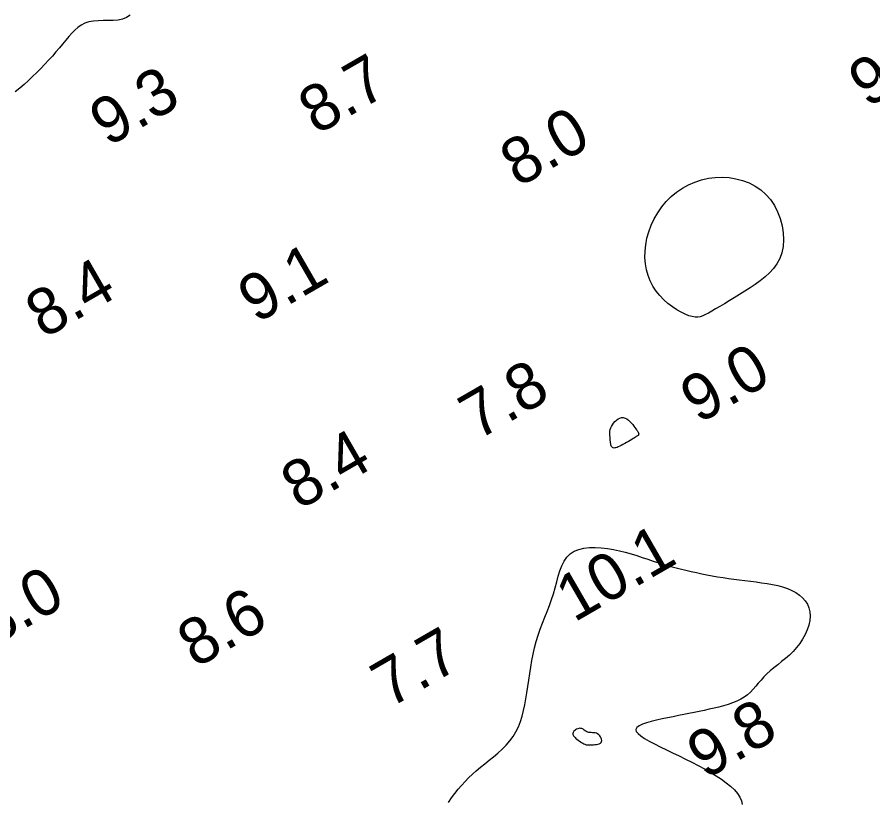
# Model space of a CAD drawing. Extents: x 3024098 to 3056816, y 418252 to 509144.
# Drawn here: x 3036706.3 to 3036798.1, y 419406.4 to 419490.6 of the extents above; entities that cross this region are included whole.
import ezdxf

# ---------------------------------------------------------------- set-up
doc = ezdxf.new("R2010")
doc.units = 0
doc.layers.add('V-CHAN-CONT-EL10', color=7, linetype='Continuous')
doc.layers.add('V-TOPO-SOUN-0911', color=7, linetype='Continuous')

msp = doc.modelspace()

# ---------------------------------------------------------------- linework, layer by layer
at = {"layer": 'V-CHAN-CONT-EL10'}
for points in [[(3036718.397, 419490.77), (3036718.028, 419490.524), (3036717.597, 419490.359), (3036717.117, 419490.264), (3036716.601, 419490.218), (3036716.064, 419490.203), (3036715.519, 419490.2), (3036714.982, 419490.19), (3036714.466, 419490.153), (3036713.985, 419490.07), (3036713.55, 419489.928), (3036713.157, 419489.728), (3036712.795, 419489.476), (3036712.457, 419489.18), (3036712.133, 419488.846), (3036711.815, 419488.48), (3036711.495, 419488.09), (3036711.162, 419487.681), (3036710.812, 419487.26), (3036710.442, 419486.83), (3036710.056, 419486.393), (3036709.654, 419485.952), (3036709.239, 419485.508), (3036708.813, 419485.065), (3036708.377, 419484.625), (3036707.933, 419484.191), (3036707.482, 419483.764), (3036707.022, 419483.349), (3036706.55, 419482.949), (3036706.062, 419482.567)], [(3036752.581, 419406.217), (3036752.921, 419406.715), (3036753.266, 419407.187), (3036753.62, 419407.634), (3036753.983, 419408.059), (3036754.358, 419408.467), (3036754.746, 419408.861), (3036755.149, 419409.245), (3036755.57, 419409.622), (3036756.01, 419409.996), (3036756.47, 419410.371), (3036756.942, 419410.749), (3036757.416, 419411.135), (3036757.885, 419411.533), (3036758.339, 419411.945), (3036758.768, 419412.375), (3036759.165, 419412.828), (3036759.519, 419413.305), (3036759.825, 419413.811), (3036760.085, 419414.343), (3036760.305, 419414.902), (3036760.491, 419415.483), (3036760.648, 419416.087), (3036760.782, 419416.71), (3036760.899, 419417.352), (3036761.005, 419418.011), (3036761.104, 419418.684), (3036761.202, 419419.368), (3036761.302, 419420.06), (3036761.409, 419420.756), (3036761.528, 419421.453), (3036761.663, 419422.147), (3036761.817, 419422.835), (3036761.996, 419423.513), (3036762.201, 419424.178), (3036762.428, 419424.832), (3036762.67, 419425.478), (3036762.919, 419426.116), (3036763.169, 419426.75), (3036763.412, 419427.381), (3036763.641, 419428.013), (3036763.85, 419428.646), (3036764.035, 419429.282), (3036764.204, 419429.911), (3036764.373, 419430.522), (3036764.552, 419431.104), (3036764.757, 419431.646), (3036764.999, 419432.138), (3036765.292, 419432.568), (3036765.649, 419432.925), (3036766.078, 419433.201), (3036766.573, 419433.4), (3036767.123, 419433.53), (3036767.716, 419433.597), (3036768.34, 419433.609), (3036768.985, 419433.574), (3036769.639, 419433.498), (3036770.291, 419433.388), (3036770.931, 419433.252), (3036771.56, 419433.094), (3036772.178, 419432.919), (3036772.787, 419432.732), (3036773.387, 419432.538), (3036773.981, 419432.341), (3036774.57, 419432.146), (3036775.155, 419431.957), (3036775.737, 419431.779), (3036776.317, 419431.612), (3036776.895, 419431.454), (3036777.471, 419431.306), (3036778.045, 419431.166), (3036778.619, 419431.035), (3036779.191, 419430.91), (3036779.763, 419430.793), (3036780.335, 419430.681), (3036780.907, 419430.575), (3036781.48, 419430.474), (3036782.056, 419430.379), (3036782.635, 419430.289), (3036783.218, 419430.203), (3036783.806, 419430.123), (3036784.4, 419430.047), (3036784.999, 419429.975), (3036785.6, 419429.902), (3036786.198, 419429.825), (3036786.788, 419429.739), (3036787.364, 419429.638), (3036787.922, 419429.519), (3036788.456, 419429.376), (3036788.961, 419429.206), (3036789.433, 419429.004), (3036789.866, 419428.769), (3036790.256, 419428.502), (3036790.597, 419428.204), (3036790.885, 419427.873), (3036791.113, 419427.511), (3036791.279, 419427.117), (3036791.376, 419426.692), (3036791.4, 419426.237), (3036791.357, 419425.758), (3036791.25, 419425.265), (3036791.086, 419424.764), (3036790.869, 419424.265), (3036790.604, 419423.776), (3036790.298, 419423.304), (3036789.954, 419422.857), (3036789.579, 419422.443), (3036789.181, 419422.056), (3036788.767, 419421.694), (3036788.347, 419421.349), (3036787.929, 419421.016), (3036787.521, 419420.691), (3036787.131, 419420.367), (3036786.768, 419420.041), (3036786.438, 419419.707), (3036786.134, 419419.369), (3036785.846, 419419.032), (3036785.565, 419418.701), (3036785.283, 419418.381), (3036784.989, 419418.076), (3036784.675, 419417.791), (3036784.331, 419417.531), (3036783.95, 419417.299), (3036783.534, 419417.094), (3036783.088, 419416.912), (3036782.616, 419416.749), (3036782.124, 419416.603), (3036781.614, 419416.469), (3036781.092, 419416.345), (3036780.563, 419416.228), (3036780.03, 419416.113), (3036779.492, 419416), (3036778.949, 419415.888), (3036778.399, 419415.776), (3036777.841, 419415.664), (3036777.273, 419415.55), (3036776.695, 419415.434), (3036776.105, 419415.315), (3036775.505, 419415.192), (3036774.913, 419415.063), (3036774.35, 419414.927), (3036773.837, 419414.781), (3036773.395, 419414.624), (3036773.045, 419414.455), (3036772.807, 419414.27), (3036772.703, 419414.069), (3036772.747, 419413.85), (3036772.93, 419413.613), (3036773.233, 419413.361), (3036773.64, 419413.093), (3036774.135, 419412.811), (3036774.699, 419412.516), (3036775.317, 419412.209), (3036775.971, 419411.892), (3036776.646, 419411.565), (3036777.334, 419411.229), (3036778.026, 419410.886), (3036778.716, 419410.536), (3036779.397, 419410.179), (3036780.061, 419409.818), (3036780.701, 419409.453), (3036781.311, 419409.085), (3036781.882, 419408.714), (3036782.406, 419408.34), (3036782.875, 419407.963), (3036783.281, 419407.582), (3036783.615, 419407.197), (3036783.868, 419406.807), (3036784.033, 419406.411), (3036784.101, 419406.009)]]:
    msp.add_lwpolyline(points, dxfattribs=at)
for points in [[(3036774.524, 419461.673), (3036774.238, 419462.232), (3036774.009, 419462.822), (3036773.838, 419463.44), (3036773.725, 419464.082), (3036773.673, 419464.745), (3036773.683, 419465.424), (3036773.755, 419466.117), (3036773.893, 419466.82), (3036774.092, 419467.523), (3036774.353, 419468.22), (3036774.672, 419468.902), (3036775.048, 419469.56), (3036775.478, 419470.186), (3036775.96, 419470.771), (3036776.493, 419471.307), (3036777.074, 419471.787), (3036777.697, 419472.207), (3036778.356, 419472.566), (3036779.044, 419472.863), (3036779.756, 419473.095), (3036780.486, 419473.26), (3036781.226, 419473.357), (3036781.971, 419473.384), (3036782.714, 419473.34), (3036783.446, 419473.223), (3036784.16, 419473.034), (3036784.847, 419472.771), (3036785.498, 419472.435), (3036786.104, 419472.025), (3036786.657, 419471.54), (3036787.149, 419470.981), (3036787.571, 419470.348), (3036787.92, 419469.658), (3036788.194, 419468.927), (3036788.391, 419468.172), (3036788.509, 419467.411), (3036788.544, 419466.662), (3036788.496, 419465.94), (3036788.36, 419465.265), (3036788.138, 419464.648), (3036787.838, 419464.088), (3036787.469, 419463.576), (3036787.041, 419463.105), (3036786.566, 419462.67), (3036786.053, 419462.261), (3036785.512, 419461.873), (3036784.953, 419461.498), (3036784.387, 419461.13), (3036783.821, 419460.771), (3036783.263, 419460.425), (3036782.72, 419460.095), (3036782.2, 419459.783), (3036781.711, 419459.493), (3036781.259, 419459.229), (3036780.853, 419458.993), (3036780.496, 419458.789), (3036780.18, 419458.62), (3036779.89, 419458.488), (3036779.614, 419458.398), (3036779.339, 419458.351), (3036779.051, 419458.351), (3036778.739, 419458.401), (3036778.388, 419458.504), (3036777.99, 419458.663), (3036777.553, 419458.874), (3036777.092, 419459.138), (3036776.618, 419459.45), (3036776.145, 419459.81), (3036775.687, 419460.214), (3036775.255, 419460.661), (3036774.864, 419461.148)], [(3036770.144, 419444.392), (3036770.095, 419444.461), (3036770.055, 419444.543), (3036770.023, 419444.631), (3036769.998, 419444.724), (3036769.98, 419444.816), (3036769.967, 419444.904), (3036769.958, 419444.983), (3036769.952, 419445.05), (3036769.948, 419445.108), (3036769.945, 419445.161), (3036769.944, 419445.212), (3036769.942, 419445.265), (3036769.938, 419445.325), (3036769.933, 419445.394), (3036769.925, 419445.476), (3036769.914, 419445.575), (3036769.904, 419445.69), (3036769.897, 419445.819), (3036769.9, 419445.96), (3036769.914, 419446.113), (3036769.945, 419446.275), (3036769.996, 419446.444), (3036770.071, 419446.62), (3036770.173, 419446.799), (3036770.3, 419446.976), (3036770.447, 419447.142), (3036770.61, 419447.291), (3036770.786, 419447.415), (3036770.971, 419447.506), (3036771.161, 419447.557), (3036771.351, 419447.561), (3036771.539, 419447.513), (3036771.721, 419447.421), (3036771.897, 419447.293), (3036772.063, 419447.142), (3036772.219, 419446.975), (3036772.362, 419446.805), (3036772.489, 419446.64), (3036772.6, 419446.49), (3036772.693, 419446.365), (3036772.769, 419446.262), (3036772.83, 419446.178), (3036772.878, 419446.111), (3036772.914, 419446.057), (3036772.942, 419446.012), (3036772.961, 419445.974), (3036772.976, 419445.94), (3036772.986, 419445.907), (3036772.994, 419445.874), (3036772.998, 419445.842), (3036773.001, 419445.812), (3036773.001, 419445.783), (3036772.999, 419445.758), (3036772.996, 419445.734), (3036772.992, 419445.715), (3036772.987, 419445.698), (3036772.982, 419445.685), (3036772.976, 419445.674), (3036772.97, 419445.666), (3036772.963, 419445.659), (3036772.955, 419445.653), (3036772.947, 419445.648), (3036772.938, 419445.642), (3036772.928, 419445.636), (3036772.914, 419445.628), (3036772.892, 419445.614), (3036772.86, 419445.594), (3036772.813, 419445.565), (3036772.748, 419445.525), (3036772.663, 419445.472), (3036772.552, 419445.404), (3036772.415, 419445.32), (3036772.256, 419445.222), (3036772.079, 419445.115), (3036771.891, 419445.001), (3036771.697, 419444.886), (3036771.502, 419444.773), (3036771.312, 419444.666), (3036771.132, 419444.568), (3036770.966, 419444.484), (3036770.816, 419444.413), (3036770.681, 419444.358), (3036770.559, 419444.319), (3036770.452, 419444.296), (3036770.357, 419444.292), (3036770.274, 419444.306), (3036770.203, 419444.339)], [(3036767.989, 419412.418), (3036768.143, 419412.424), (3036768.306, 419412.434), (3036768.47, 419412.451), (3036768.627, 419412.479), (3036768.769, 419412.522), (3036768.887, 419412.581), (3036768.974, 419412.66), (3036769.024, 419412.761), (3036769.038, 419412.879), (3036769.019, 419413.008), (3036768.973, 419413.141), (3036768.903, 419413.272), (3036768.813, 419413.394), (3036768.706, 419413.502), (3036768.586, 419413.587), (3036768.458, 419413.647), (3036768.323, 419413.685), (3036768.185, 419413.707), (3036768.046, 419413.718), (3036767.909, 419413.724), (3036767.776, 419413.73), (3036767.65, 419413.744), (3036767.535, 419413.769), (3036767.43, 419413.811), (3036767.335, 419413.866), (3036767.247, 419413.929), (3036767.162, 419413.994), (3036767.078, 419414.057), (3036766.992, 419414.113), (3036766.9, 419414.156), (3036766.8, 419414.182), (3036766.69, 419414.186), (3036766.574, 419414.17), (3036766.455, 419414.137), (3036766.339, 419414.089), (3036766.23, 419414.028), (3036766.132, 419413.959), (3036766.05, 419413.883), (3036765.988, 419413.803), (3036765.95, 419413.721), (3036765.936, 419413.638), (3036765.943, 419413.553), (3036765.971, 419413.467), (3036766.019, 419413.38), (3036766.084, 419413.291), (3036766.166, 419413.2), (3036766.263, 419413.107), (3036766.373, 419413.014), (3036766.493, 419412.92), (3036766.619, 419412.829), (3036766.747, 419412.742), (3036766.874, 419412.661), (3036766.996, 419412.589), (3036767.108, 419412.526), (3036767.207, 419412.476), (3036767.291, 419412.44), (3036767.364, 419412.416), (3036767.43, 419412.402), (3036767.496, 419412.396), (3036767.565, 419412.396), (3036767.644, 419412.401), (3036767.738, 419412.407), (3036767.852, 419412.413)]]:
    msp.add_lwpolyline(points, close=True, dxfattribs=at)

# ---------------------------------------------------------------- texts
at = {"layer": 'V-TOPO-SOUN-0911'}
for s, p in [('9.1', (3036797.498, 419480.773)), ('8.7', (3036738.427, 419477.871)), ('9.3', (3036716.017, 419476.591)), ('8.0', (3036760.075, 419472.221)), ('9.1', (3036731.948, 419457.613)), ('8.4', (3036709.127, 419455.981)), ('9.0', (3036779.435, 419446.831)), ('7.8', (3036755.687, 419445.061)), ('8.4', (3036736.557, 419437.581)), ('10.1 ', (3036766.068, 419425.513)), ('8.0', (3036703.645, 419422.881)), ('8.6', (3036725.435, 419420.592)), ('7.7', (3036746.237, 419416.291)), ('9.8', (3036780.157, 419408.641))]:
    msp.add_text(s, height=5, rotation=30, dxfattribs=at).set_placement(p)

doc.saveas('drawing.dxf')
